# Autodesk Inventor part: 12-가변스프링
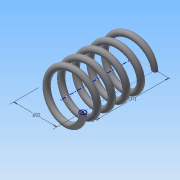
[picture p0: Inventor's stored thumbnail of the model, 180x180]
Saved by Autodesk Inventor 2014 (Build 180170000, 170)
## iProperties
Created: 2015-09
Part Number: 12-가변스프링
Material: Generic
Document SubType Name: Modeling
Designer: study
Density: 1 g/cm^3
Appearance: Default
Author: study
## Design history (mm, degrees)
sketch "스케치1"
  geometry: L1 (0, 0)-(11, 0); L2 (11, 0)-(11, 26.495); L3 (11, 26.495)-(0, 26.495); L4 (0, 26.495)-(0, 0); C1 r 1.5 at (11, 0); 1 further point
  constraints: 8 end point, 2 coincident, 2 parallel, 1 centre point, 1 horizontal, 1 perpendicular
  dimensions: "d0" = 22 diameter of L2 L4; "d1" = 26.4955 distance between parallel lines of L1 L3 (derived); "d2" = 3 diameter of C1
feature "코일1" sketch "스케치1" pitch "d3" = 10; turns "d5" = 5; dims "d4" = 26.4955 (= d1), "d6" = 0, angle "d7" = 90 deg, angle "d8" = 90 deg, "d9" = 0, "d10" = 0
node "작업 평면1"
sketch "스케치2"
  geometry: L1 (-12.5, 0)-(-9.5, 0) reference; 1 further point
  constraints: 1 horizontal alignment
extrude "돌출1" cut sketch "스케치2" stored distance "d12" = 10; taper "d13" = 0 deg
node "작업 평면2"
sketch "스케치3"
  geometry: L1 (-9.5, 0)-(-12.5, 0) reference; 1 further point
  constraints: 1 horizontal alignment
extrude "돌출2" cut sketch "스케치3" stored distance "d15" = 10; taper "d16" = 0 deg
node "솔리드1"
node "절단 모서리 투영1"
node "절단 모서리 투영2"
other parameters: "d11" = 0, "d14" = 26.4955 (= d1)
